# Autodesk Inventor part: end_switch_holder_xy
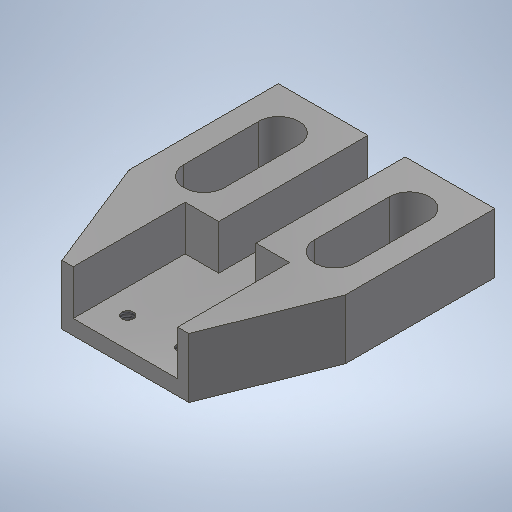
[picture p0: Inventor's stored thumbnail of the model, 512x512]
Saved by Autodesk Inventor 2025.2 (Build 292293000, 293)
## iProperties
Created: 2025-04
Part Number: end_switch_holder_xy
Material: 1.0037 S235JR
Document SubType Name: Modeling
Designer: BennF
Density: 7.85 g/cm^3
Appearance: Stahl
Author: BennF
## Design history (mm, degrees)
sketch "Sketch2"
  geometry: L1 (-14.5, 20)-(14.5, 20); L2 (-8.75, 14.3)-(-8.75, 4.3); L3 (-11.45, 14.3)-(-11.45, 4.3); L4 (-6.05, 4.3)-(-6.05, 14.3); L5 (8.75, 14.3)-(8.75, 4.3); L6 (6.05, 14.3)-(6.05, 4.3); L7 (11.45, 4.3)-(11.45, 14.3); L8 (-8.75, 9.3)-(8.75, 9.3); L9 (-14.5, 20)-(-14.5, 0); L10 (-14.5, 0)-(-8.5, -15); L11 (-8.5, -15)-(8.5, -15); L12 (8.5, -15)-(14.5, 0); L13 (14.5, 0)-(14.5, 20); A1 r 2.7 centre (-8.75, 14.3) between (-6.05, 14.3) and (-11.45, 14.3); A2 r 2.7 centre (-8.75, 4.3) between (-11.45, 4.3) and (-6.05, 4.3); A3 r 2.7 centre (8.75, 14.3) between (11.45, 14.3) and (6.05, 14.3); A4 r 2.7 centre (8.75, 4.3) between (6.05, 4.3) and (11.45, 4.3); 5 further points
  constraints: 30 end point, 9 point on circle, 8 tangent, 5 midpoint, 4 centre point, 4 horizontal alignment, 4 parallel, 3 vertical alignment, 2 perpendicular, 2 vertical, 1 equal radius, 1 horizontal
  dimensions: "d0" = 29 distance of L1.start L1.end; "d1" = 17.5 distance of L8.start L8.end; "d2" = 2.7 radius of A2; "d3" = 10 distance of L2.start L2.end; "d4" = 3 distance from line of L1 point (-8.75, 17); "d5" = 20 distance of L1.start L9.end; "d6" = 17 distance of L10.end L11.end; "d7" = 15 distance from line of L11 L9.end
extrude "Extrusion1" new body sketch "Sketch2" distance "d8" = 8; taper "d9" = 0 deg
sketch "Sketch3"
  geometry: L1 (-2.5, 20)-(-2.5, 0); L2 (14.5, 20)-(-14.5, 20) reference; L3 (2.5, 20)-(2.5, 0); L4 (-2.5, 0)-(-7, 0); L5 (-7, 0)-(-7, -15); L6 (2.5, 0)-(7, 0); L7 (7, 0)-(7, -15); L8 (-8.5, -15)-(8.5, -15) reference; L9 (-2.5, 0)-(2.5, 0); 3 further points
  constraints: 14 end point, 5 point on line, 3 equal length, 3 perpendicular, 2 horizontal, 2 vertical, 1 coincident, 1 midpoint
  dimensions: "d10" = 15 distance of L4.end L5.end; "d11" = 14 distance between parallel lines of L7 L5; "d12" = 5 distance between parallel lines of L3 L1
extrude "Extrusion2" cut sketch "Sketch3" distance "d13" = 6; taper "d14" = 0 deg
sketch "Sketch4"
  geometry: L1 (-3.7, -11)-(3.7, -11); L2 (7, -15)-(-7, -15) reference; 2 further points
  constraints: 2 end point, 1 horizontal, 1 horizontal alignment, 1 midpoint, 1 vertical alignment
  dimensions: "d22" = 7.4 distance of L1.start L1.end; "d23" = 4 distance between parallel lines of L2 L1
hole "Hole1" sketch "Sketch4" at (-3.7, -11), (3.7, -11) diameter "d15" = 1.567; stored, may be unused: countersink angle "d19" = 90 deg, drill point angle "d21" = 118 deg; dims "d16" = 4, "d17" = 4, "d18" = 2, "d20" = 8
body "Solid1"
